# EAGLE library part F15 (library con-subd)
SUB-D
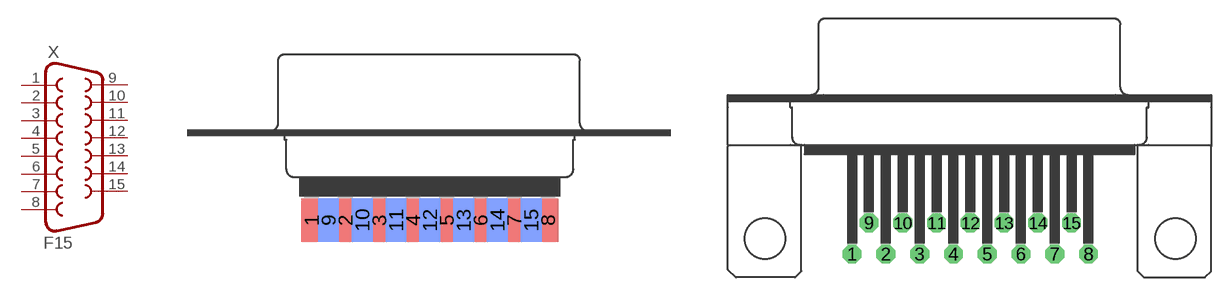
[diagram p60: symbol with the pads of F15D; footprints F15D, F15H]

Designator prefix X

## F15D (OC_FARNELL: unknown; OC_NEWARK: unknown)  [F15D]
1  1  pas
2  2  pas
3  3  pas
4  4  pas
5  5  pas
6  6  pas
7  7  pas
8  8  pas
9  9  pas
10  10  pas
11  11  pas
12  12  pas
13  13  pas
14  14  pas
15  15  pas

## F15H (OC_FARNELL: unknown; OC_NEWARK: unknown)  [F15H]
Pads as for F15D

## F15HP (OC_FARNELL: unknown; OC_NEWARK: unknown)  [F15HP]
Pads as for F15D

## F15V (OC_FARNELL: unknown; OC_NEWARK: unknown)  [F15V]
Pads as for F15D

## F15VP (OC_FARNELL: unknown; OC_NEWARK: unknown)  [F15VP]
Pads as for F15D

## F15HDH (OC_FARNELL: unknown; OC_NEWARK: unknown)  [HDF15H]
Pads as for F15D

## F15HDV (OC_FARNELL: unknown; OC_NEWARK: unknown)  [HDF15V]
Pads as for F15D

## F15VB (OC_FARNELL: unknown; OC_NEWARK: unknown)  [F15VB]
Pads as for F15D

## Footprint F15D (pad centres in mm)
SUB-D
smd 1.7 x 3.5: 1 -9.601,-6.045; 2 -6.858,-6.045; 3 -4.115,-6.045; 4 -1.372,-6.045; 5 1.372,-6.045; 6 4.115,-6.045; 7 6.858,-6.045; 8 9.601,-6.045
smd 1.7 x 3.5 bottom: 9 -8.23,-6.045; 10 -5.486,-6.045; 11 -2.743,-6.045; 12 0,-6.045; 13 2.743,-6.045; 14 5.486,-6.045; 15 8.23,-6.045

## Footprint F15H (pad centres in mm)
SUB-D
drill 1.016 octagon: 1 -9.601,-1.27; 2 -6.858,-1.27; 3 -4.115,-1.27; 4 -1.372,-1.27; 5 1.372,-1.27; 6 4.115,-1.27; 7 6.858,-1.27; 8 9.601,-1.27; 9 -8.23,1.27; 10 -5.486,1.27; 11 -2.743,1.27; 12 0,1.27; 13 2.743,1.27; 14 5.486,1.27; 15 8.23,1.27
hole 3.302 at -16.662,0
hole 3.302 at 16.662,0

## Footprint F15HP (pad centres in mm)
SUB-D
drill 1.016 octagon: 1 -9.601,-1.27; 2 -6.858,-1.27; 3 -4.115,-1.27; 4 -1.372,-1.27; 5 1.372,-1.27; 6 4.115,-1.27; 7 6.858,-1.27; 8 9.601,-1.27; 9 -8.23,1.27; 10 -5.486,1.27; 11 -2.743,1.27; 12 0,1.27; 13 2.743,1.27; 14 5.486,1.27; 15 8.23,1.27
drill 3.302 pad 5.08 round: G1 -16.662,0; G2 16.662,0

## Footprint F15V (pad centres in mm)
SUB-D
drill 1.016 octagon: 1 9.601,1.422; 2 6.858,1.422; 3 4.115,1.422; 4 1.372,1.422; 5 -1.372,1.422; 6 -4.115,1.422; 7 -6.858,1.422; 8 -9.601,1.422; 9 8.23,-1.422; 10 5.486,-1.422; 11 2.743,-1.422; 12 0,-1.422; 13 -2.743,-1.422; 14 -5.486,-1.422; 15 -8.23,-1.422
hole 3.302 at 16.662,0
hole 3.302 at -16.662,0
